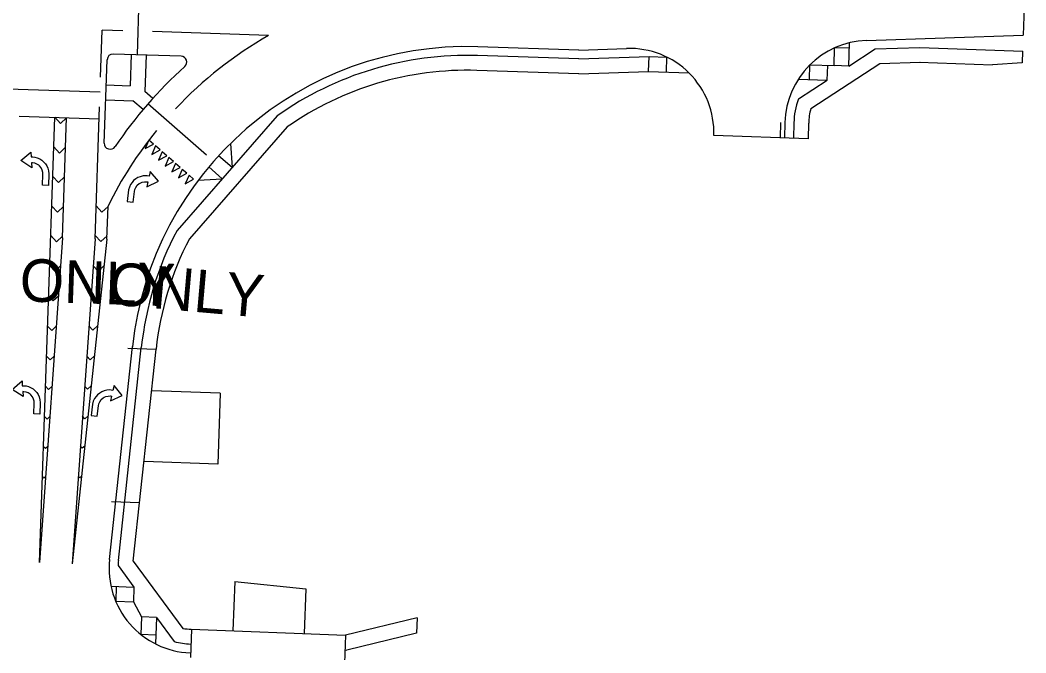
# Model space of a CAD drawing. Extents: x 979036 to 996074, y 1836928 to 1845163.
# Drawn here: x 992489.6 to 992829.2, y 1843156.7 to 1843370.6 of the extents above; entities that cross this region are included whole.
import ezdxf

# ---------------------------------------------------------------- set-up
doc = ezdxf.new("R2010")
doc.units = 0
for name, color, linetype in [('R_Proposed Road', 7, 'Continuous'), ('STRIPE_White Crosswalk', 7, 'Continuous'), ('STRIPE_White Stopbar', 7, 'Continuous'), ('STRIPE_White Turn Arrow', 7, 'Continuous'), ('STRIPE_White_6in', 7, 'Continuous'), ('STRIPE_White_ONLY', 7, 'Continuous'), ('STRIPE_White_Yield Tri', 7, 'Continuous')]:
    doc.layers.add(name, color=color, linetype=linetype)

msp = doc.modelspace()

# ---------------------------------------------------------------- linework, layer by layer
at = {"layer": 'R_Proposed Road'}
for p, q in [((992829.16, 1843392.5), (992828.27, 1843365.51)), ((992769.39, 1843355.06), (992769.65, 1843362.95)), ((992775.34, 1843363.72), (992828.27, 1843365.51)), ((992543.92, 1843358.34), (992520.99, 1843359.1)), ((992678.16, 1843360.44), (992644.07, 1843361.56)), ((992678.26, 1843360.44), (992694.35, 1843360.98)), ((992764.39, 1843355.22), (992764.59, 1843361.22)), ((992769.59, 1843361.06), (992764.59, 1843361.22)), ((992769.39, 1843355.06), (992778.22, 1843360.82)), ((992778.22, 1843360.82), (992793.32, 1843361.33)), ((992793.32, 1843361.33), (992828.1, 1843360.09)), ((992827.97, 1843356.1), (992828.1, 1843360.09)), ((992517.96, 1843329.01), (992518.93, 1843357.17)), ((992527.1, 1843358.9), (992526.76, 1843348.39)), ((992532.1, 1843358.73), (992531.7, 1843346.46)), ((992678.21, 1843357.44), (992643.98, 1843358.56)), ((992678.21, 1843357.44), (992701.94, 1843358.24)), ((992701.77, 1843353.24), (992701.94, 1843358.24)), ((992701.94, 1843358.24), (992707.93, 1843358.04)), ((992707.77, 1843353.05), (992707.93, 1843358.04)), ((992756.55, 1843340.72), (992779.79, 1843355.87)), ((992779.79, 1843355.87), (992793.49, 1843356.33)), ((992793.15, 1843356.33), (992817.94, 1843355.45)), ((992827.95, 1843356.1), (992817.94, 1843355.43)), ((992678.21, 1843352.43), (992643.81, 1843353.56)), ((992678.21, 1843352.43), (992701.77, 1843353.23)), ((992701.77, 1843353.24), (992715.32, 1843352.8)), ((992756.09, 1843350.49), (992756.25, 1843355.49)), ((992756.25, 1843355.49), (992764.39, 1843355.22)), ((992762.08, 1843350.3), (992762.25, 1843355.29)), ((992769.39, 1843355.06), (992764.39, 1843355.22)), ((992752.31, 1843350.62), (992762.08, 1843350.3)), ((992752.34, 1843343.94), (992762.08, 1843350.3)), ((992518.64, 1843348.67), (992526.76, 1843348.39)), ((992534.37, 1843344.13), (992531.7, 1843346.46)), ((992518.46, 1843343.67), (992527.66, 1843343.35)), ((992531.08, 1843340.36), (992527.66, 1843343.35)), ((992576.36, 1843338.21), (992542.54, 1843299.53)), ((992746.32, 1843335.98), (992746.19, 1843330.8)), ((992747.82, 1843335.94), (992747.69, 1843330.76)), ((992750.82, 1843335.87), (992750.69, 1843330.69)), ((992755.81, 1843335.74), (992755.68, 1843330.48)), ((992579.73, 1843334.47), (992546.7, 1843296.69)), ((992560.55, 1843328.84), (992561.1, 1843320.75)), ((992755.68, 1843330.48), (992723.8, 1843331.55)), ((992561.1, 1843320.75), (992556.58, 1843324.7)), ((992557.8, 1843316.99), (992553.29, 1843320.94)), ((992549.72, 1843316.45), (992557.8, 1843316.99)), ((992519.78, 1843188.27), (992527.5, 1843260.23)), ((992522.76, 1843187.95), (992530.48, 1843259.91)), ((992535.44, 1843259.3), (992525.92, 1843259.63)), ((992527.77, 1843187.73), (992535.45, 1843259.37)), ((992557.09, 1843244.55), (992534.02, 1843245.34)), ((992557.09, 1843244.55), (992556.27, 1843220.56)), ((992556.27, 1843220.56), (992531.45, 1843221.42)), ((992529.88, 1843207.46), (992520.36, 1843207.79)), ((992522.64, 1843186.26), (992527.99, 1843179.01)), ((992527.77, 1843187.73), (992544.53, 1843165.04)), ((992520.24, 1843179.28), (992527.99, 1843179.01)), ((992522, 1843179.22), (992521.83, 1843174.22)), ((992562.07, 1843180.85), (992561.43, 1843164.2)), ((992562.07, 1843180.85), (992585.99, 1843178.39)), ((992527.99, 1843179.01), (992527.82, 1843174.01)), ((992585.99, 1843178.39), (992585.41, 1843163.27)), ((992521.83, 1843174.22), (992527.82, 1843174.01)), ((992527.82, 1843174.01), (992530.59, 1843168.93)), ((992530.59, 1843168.93), (992530.36, 1843162.94)), ((992535.58, 1843168.74), (992530.59, 1843168.93)), ((992535.58, 1843168.74), (992535.24, 1843159.8)), ((992535.58, 1843168.74), (992541.62, 1843160.57)), ((992623.64, 1843168.59), (992599.4, 1843162.73)), ((992623.64, 1843168.59), (992623.44, 1843163.4)), ((992535.35, 1843162.74), (992530.36, 1843162.94)), ((992547.44, 1843164.74), (992547.07, 1843155.25)), ((992547.32, 1843164.74), (992599.4, 1843162.73)), ((992599.4, 1843162.73), (992599.03, 1843153.24)), ((992623.44, 1843163.4), (992599.9, 1843157.71)), ((992547.13, 1843159.75), (992547.25, 1843159.74)), ((992599.21, 1843157.73), (992599.9, 1843157.71))]:
    msp.add_line(p, q, dxfattribs=at)
for centre, radius, start, end in [((992776.31, 1843335.24), 28.5, 91.9369, 178.589), ((992520.93, 1843357.1), 2, 88.1194, 178.0361), ((992640.35, 1843248.12), 113.5, 88.1194, 173.8765), ((992695.32, 1843332.5), 28.5, 358.0857, 91.9369), ((992543.85, 1843356.35), 2, 311.7223, 88.1194), ((992640.35, 1843248.12), 110.5, 88.1194, 125.3859), ((992640.35, 1843248.12), 143, 131.7223, 146.1268), ((992640.35, 1843248.12), 105.5, 88.1194, 125.0696), ((992776.31, 1843335.24), 25.5, 160.0559, 178.589), ((992776.31, 1843335.24), 20.5, 164.4998, 178.589), ((992519.96, 1843328.94), 2, 178.0361, 326.1268), ((992640.35, 1843248.12), 110.5, 152.272, 173.8765), ((992640.35, 1843248.12), 105.5, 152.5884, 173.8765), ((992548.11, 1843185.23), 28.5, 173.8765, 267.7861), ((992548.11, 1843185.23), 25.5, 173.8765, 177.675), ((992548.11, 1843185.23), 20.5, 259.9356, 267.7861), ((992548.11, 1843185.23), 25.5, 255.2493, 267.7861)]:
    msp.add_arc(centre, radius, start, end, dxfattribs=at)
at = {"layer": 'STRIPE_White Crosswalk'}
for p, q in [((992530.65, 1843408.15), (992529.03, 1843358.83)), ((992466.81, 1843347.94), (992516.55, 1843346.31)), ((992552.54, 1843324.92), (992532.71, 1843342.26))]:
    msp.add_line(p, q, dxfattribs=at)
at = {"layer": 'STRIPE_White Stopbar'}
msp.add_line((992489.26, 1843338.17), (992516.24, 1843337.24), dxfattribs=at)
at = {"layer": 'STRIPE_White Turn Arrow'}
for points in [[(992493.46, 1843320.68), (992489.84, 1843323.12), (992493.12, 1843326), (992493.23, 1843324.33), (992493.9, 1843324.32), (992494.47, 1843324.26), (992495.27, 1843324.07), (992496.19, 1843323.67), (992496.91, 1843323.24), (992497.49, 1843322.67), (992498.16, 1843322.02), (992498.54, 1843321.32), (992498.94, 1843320.56), (992499.18, 1843319.61), (992499.3, 1843318.63), (992499.11, 1843314.73), (992497.11, 1843314.82), (992497.25, 1843318.41), (992497.23, 1843319.1), (992497.03, 1843319.84), (992496.68, 1843320.63), (992496.13, 1843321.29), (992495.84, 1843321.52), (992495.23, 1843321.91), (992494.48, 1843322.18), (992493.75, 1843322.32), (992493.36, 1843322.34)], [(992532.29, 1843314.27), (992536.25, 1843316.1), (992533.48, 1843319.47), (992533.11, 1843317.84), (992532.45, 1843317.93), (992531.87, 1843317.97), (992531.06, 1843317.91), (992530.08, 1843317.67), (992529.3, 1843317.35), (992528.64, 1843316.89), (992527.87, 1843316.35), (992527.39, 1843315.72), (992526.86, 1843315.04), (992526.47, 1843314.14), (992526.19, 1843313.19), (992525.75, 1843309.31), (992527.74, 1843309.08), (992528.18, 1843312.64), (992528.32, 1843313.32), (992528.63, 1843314.02), (992529.11, 1843314.75), (992529.76, 1843315.31), (992530.08, 1843315.49), (992530.74, 1843315.78), (992531.53, 1843315.92), (992532.27, 1843315.94), (992532.66, 1843315.9)], [(992490.53, 1843243.38), (992486.91, 1843245.81), (992490.19, 1843248.69), (992490.3, 1843247.03), (992490.96, 1843247.01), (992491.54, 1843246.96), (992492.33, 1843246.76), (992493.26, 1843246.37), (992493.98, 1843245.93), (992494.56, 1843245.36), (992495.23, 1843244.71), (992495.61, 1843244.01), (992496.01, 1843243.26), (992496.25, 1843242.31), (992496.37, 1843241.32), (992496.18, 1843237.42), (992494.18, 1843237.51), (992494.32, 1843241.1), (992494.3, 1843241.79), (992494.1, 1843242.54), (992493.75, 1843243.33), (992493.2, 1843243.99), (992492.9, 1843244.22), (992492.3, 1843244.61), (992491.55, 1843244.88), (992490.82, 1843245.01), (992490.43, 1843245.04)], [(992520.09, 1843241.9), (992524.06, 1843243.72), (992521.28, 1843247.09), (992520.91, 1843245.46), (992520.25, 1843245.55), (992519.67, 1843245.59), (992518.86, 1843245.53), (992517.88, 1843245.29), (992517.1, 1843244.98), (992516.44, 1843244.51), (992515.67, 1843243.97), (992515.19, 1843243.34), (992514.66, 1843242.66), (992514.27, 1843241.76), (992514, 1843240.81), (992513.55, 1843236.93), (992515.55, 1843236.7), (992515.98, 1843240.27), (992516.12, 1843240.94), (992516.44, 1843241.64), (992516.91, 1843242.37), (992517.56, 1843242.93), (992517.89, 1843243.11), (992518.54, 1843243.4), (992519.33, 1843243.54), (992520.08, 1843243.56), (992520.46, 1843243.52)]]:
    msp.add_lwpolyline(points, close=True, dxfattribs=at)
at = {"layer": 'STRIPE_White_6in'}
for p, q in [((992516.72, 1843351.31), (992517.27, 1843367.22)), ((992524.29, 1843366.99), (992517.27, 1843367.22)), ((992573.45, 1843365.38), (992534.29, 1843366.67)), ((992514.85, 1843296.66), (992516.38, 1843341.31)), ((992496.09, 1843187.24), (992501.25, 1843337.76)), ((992503.18, 1843335.67), (992501.25, 1843337.73)), ((992505.25, 1843337.6), (992503.18, 1843335.67)), ((992503.86, 1843297.04), (992505.25, 1843337.62)), ((992502.84, 1843325.67), (992500.91, 1843327.74)), ((992504.91, 1843327.6), (992502.84, 1843325.67)), ((992502.5, 1843315.68), (992500.57, 1843317.75)), ((992504.56, 1843317.61), (992502.5, 1843315.68)), ((992502.15, 1843305.68), (992500.22, 1843307.75)), ((992504.22, 1843307.61), (992502.15, 1843305.68)), ((992517.16, 1843305.7), (992515.23, 1843307.77)), ((992519.23, 1843307.63), (992517.16, 1843305.7)), ((992518.85, 1843296.52), (992519.23, 1843307.75)), ((992503.86, 1843297.04), (992496.09, 1843187.24)), ((992501.81, 1843295.69), (992499.88, 1843297.76)), ((992503.88, 1843297.62), (992501.81, 1843295.69)), ((992514.85, 1843296.66), (992507.08, 1843186.86)), ((992518.85, 1843296.52), (992507.08, 1843186.86)), ((992516.82, 1843295.71), (992514.89, 1843297.78)), ((992518.89, 1843297.64), (992516.82, 1843295.71)), ((992501.26, 1843285.7), (992499.53, 1843287.56)), ((992503.18, 1843287.49), (992501.26, 1843285.7)), ((992515.89, 1843285.73), (992514.21, 1843287.54)), ((992517.89, 1843287.6), (992515.89, 1843285.73)), ((992500.74, 1843275.71), (992499.18, 1843277.38)), ((992502.46, 1843277.32), (992500.74, 1843275.71)), ((992515, 1843275.76), (992513.49, 1843277.37)), ((992516.8, 1843277.45), (992515, 1843275.76)), ((992500.21, 1843265.73), (992498.83, 1843267.2)), ((992501.74, 1843267.16), (992500.21, 1843265.73)), ((992514.11, 1843265.78), (992512.77, 1843267.22)), ((992515.71, 1843267.28), (992514.11, 1843265.78)), ((992499.69, 1843255.74), (992498.48, 1843257.03)), ((992501.02, 1843256.99), (992499.69, 1843255.74)), ((992513.22, 1843255.81), (992512.05, 1843257.06)), ((992514.62, 1843257.12), (992513.22, 1843255.81)), ((992499.16, 1843245.75), (992498.13, 1843246.85)), ((992500.31, 1843246.82), (992499.16, 1843245.75)), ((992512.33, 1843245.83), (992511.33, 1843246.91)), ((992513.53, 1843246.95), (992512.33, 1843245.83)), ((992512.44, 1843236.79), (992511.44, 1843235.86)), ((992498.63, 1843235.76), (992497.79, 1843236.67)), ((992499.59, 1843236.65), (992498.63, 1843235.76)), ((992511.44, 1843235.86), (992510.61, 1843236.75)), ((992511.35, 1843226.62), (992510.56, 1843225.88)), ((992498.13, 1843225.78), (992497.44, 1843226.52)), ((992498.86, 1843226.46), (992498.13, 1843225.78)), ((992510.56, 1843225.88), (992509.89, 1843226.59)), ((992509.67, 1843215.91), (992509.18, 1843216.43)), ((992510.26, 1843216.46), (992509.67, 1843215.91)), ((992497.6, 1843215.79), (992497.09, 1843216.33)), ((992498.15, 1843216.3), (992497.6, 1843215.79))]:
    msp.add_line(p, q, dxfattribs=at)
for start, end in [(119.7058, 136.7412), (140.9167, 153.7867)]:
    msp.add_arc((992640.35, 1843248.12), 135, start, end, dxfattribs=at)
at = {"layer": 'STRIPE_White_Yield Tri'}
for p, q in [((992533.03, 1843330.02), (992531.76, 1843327.15)), ((992531.76, 1843327.15), (992534.54, 1843328.7)), ((992534.54, 1843328.7), (992533.03, 1843330.02)), ((992535.29, 1843328.05), (992534.02, 1843325.17)), ((992534.02, 1843325.17), (992536.79, 1843326.73)), ((992536.79, 1843326.73), (992535.29, 1843328.05)), ((992537.55, 1843326.07), (992536.28, 1843323.2)), ((992539.05, 1843324.75), (992537.55, 1843326.07)), ((992536.28, 1843323.2), (992539.05, 1843324.75)), ((992539.8, 1843324.1), (992538.53, 1843321.22)), ((992538.53, 1843321.22), (992541.31, 1843322.78)), ((992541.31, 1843322.78), (992539.8, 1843324.1)), ((992542.06, 1843322.12), (992540.79, 1843319.25)), ((992543.57, 1843320.8), (992542.06, 1843322.12)), ((992540.79, 1843319.25), (992543.57, 1843320.8)), ((992544.32, 1843320.15), (992543.05, 1843317.27)), ((992543.05, 1843317.27), (992545.83, 1843318.83)), ((992545.83, 1843318.83), (992544.32, 1843320.15)), ((992546.58, 1843318.17), (992545.31, 1843315.3)), ((992545.31, 1843315.3), (992548.09, 1843316.85)), ((992548.09, 1843316.85), (992546.58, 1843318.17))]:
    msp.add_line(p, q, dxfattribs=at)

# ---------------------------------------------------------------- texts
at = {"layer": 'STRIPE_White_ONLY'}
for rotation, p in [(358.0361, (992489.23, 1843275.6)), (354.9816, (992518.98, 1843274.6))]:
    msp.add_text('ONLY', height=14.4, rotation=rotation, dxfattribs=at).set_placement(p)

doc.saveas('drawing.dxf')
